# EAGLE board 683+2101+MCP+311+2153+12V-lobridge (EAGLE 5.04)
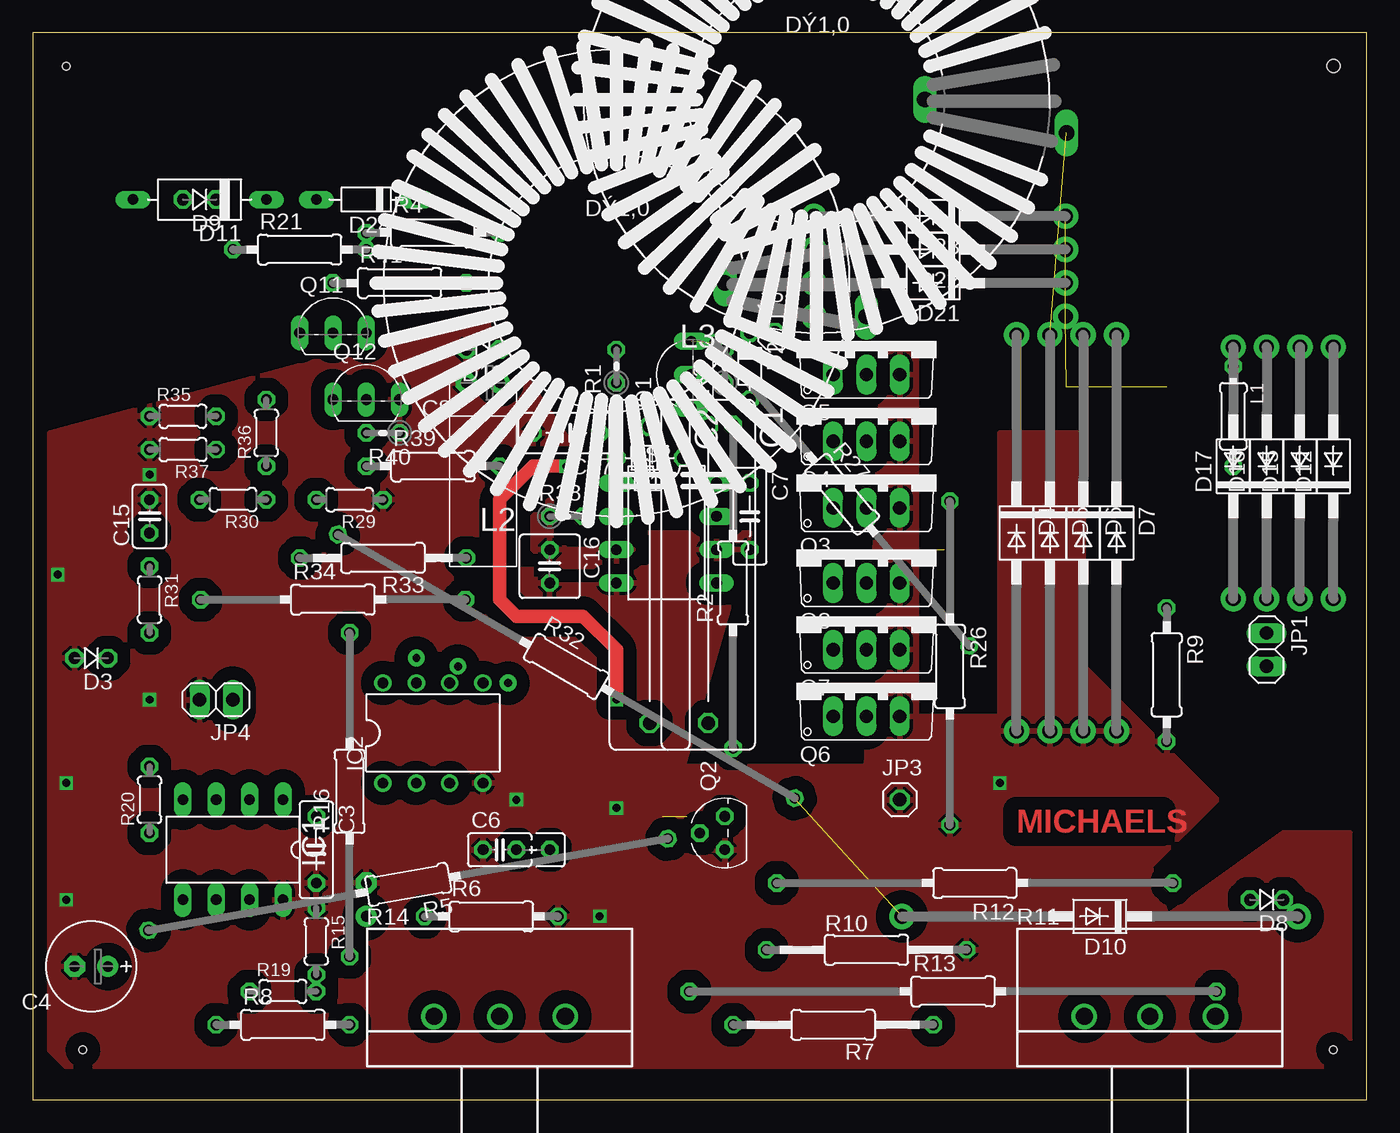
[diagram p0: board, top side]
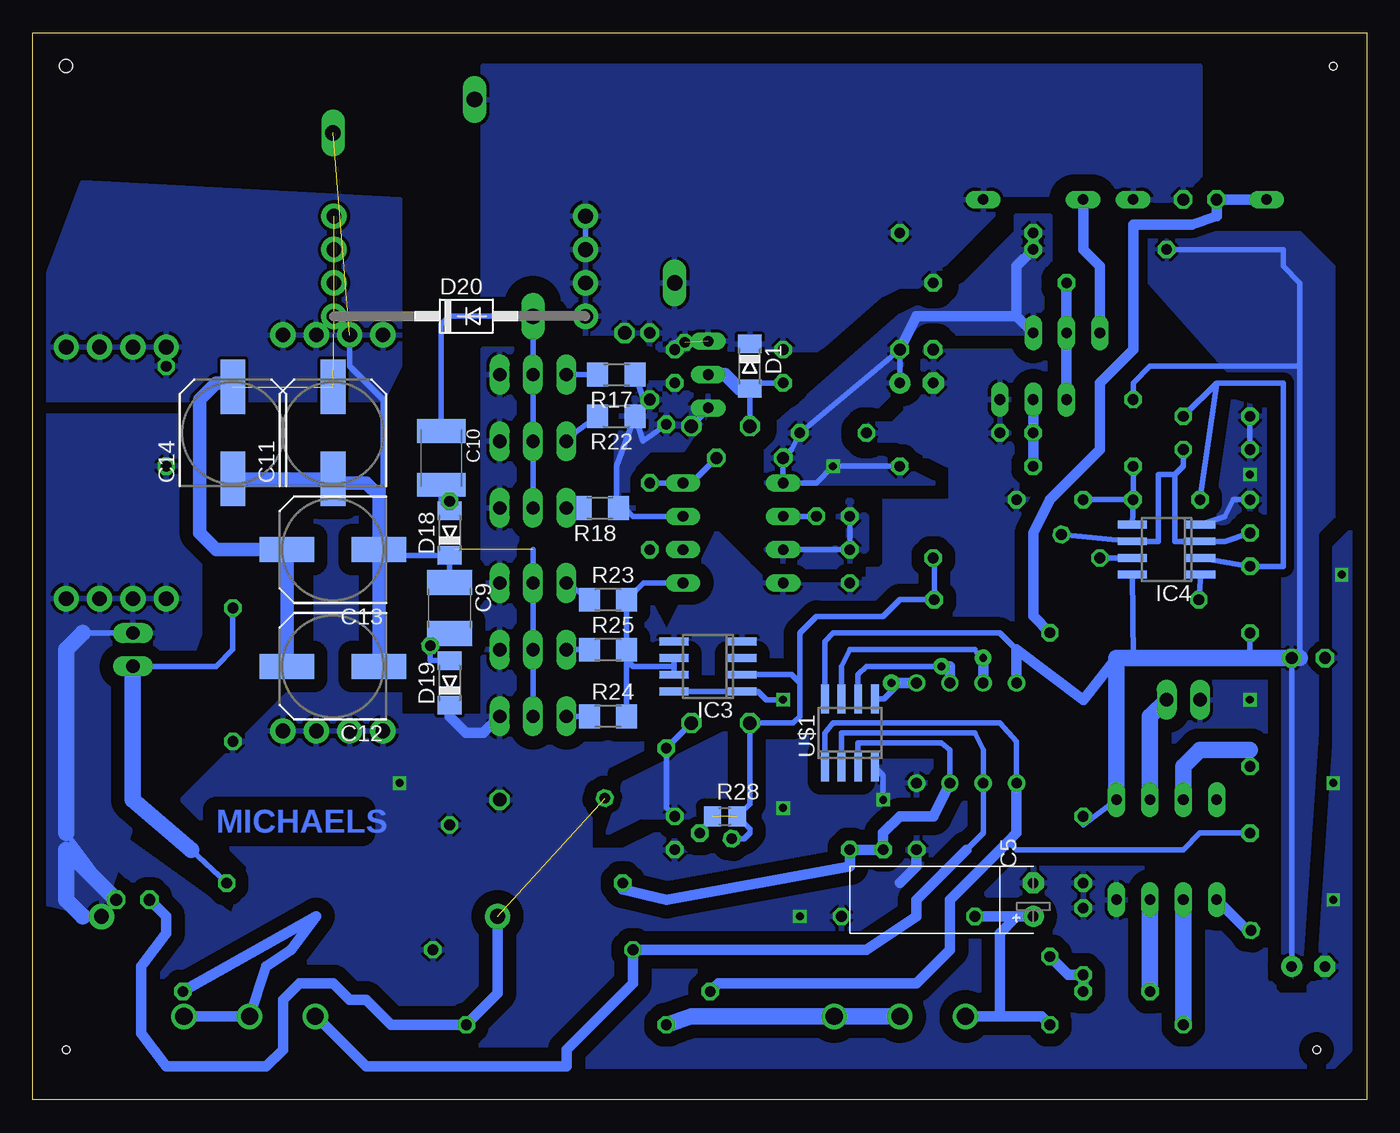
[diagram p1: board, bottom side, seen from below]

Size 101.6 x 81.28 mm. Coordinates in mm from the lower left corner, seen from the top.
Outline: 0,0 101.6,0 101.6,81.28 0,81.28 0,0
Copper layers (1*16): Top 0.035mm / dielectric 1.5mm / Bottom 0.035mm
Design rules "default": minimum track width 10mil, minimum drill 24mil, track to track 8mil, track to pad 8mil, pad to pad 8mil, via to via 8mil, smd to smd 8mil, copper to edge 40mil, drill to drill 8mil, minimum pad ring 10mil, minimum via ring 8mil, stop-mask expansion 4mil, vias tented up to drill 0mil, thermal gap 10mil
Holes 0.6 mm at 2.54,78.74 3.81,3.81 99.06,3.81
Holes 1 mm at 99.06,78.74

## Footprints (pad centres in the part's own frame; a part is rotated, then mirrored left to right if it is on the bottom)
C225-074X268 = drill 1.016 octagon: 1 -11.303,0; 2 11.303,0
C225-062X268 = drill 1.016 octagon: 1 -11.303,0; 2 11.303,0
C050-025X075 = drill 0.813 octagon: 1 -2.54,0; 2 2.54,0
E2,5-7 = drill 0.813 pad 1.6 round: + -1.27,0 | drill 0.813 pad 1.6 octagon: - 1.27,0
2,5-5-FLAT = drill 0.813 pad 1.6 round: + -1.27,0 | drill 0.813 pad 1.6 octagon: - 1.27,0
C025_050-025X075 = drill 0.813 octagon: 1 -1.27,0; 2 1.27,0; 3 3.81,0
C1812 = smd 1.9 x 3.4: 1 -1.95,0; 2 1.95,0
C1812K = smd 1.8 x 3.7: 1 -2.05,0; 2 2.05,0
SANYO-OSCON_SMD_E7 = smd 4.15 x 1.9: + 3.5,0; - -3.5,0
C025-025X050 = drill 0.813 octagon: 1 -1.27,0; 2 1.27,0
C025-050X050 = drill 0.813 octagon: 1 -1.27,0; 2 1.27,0
C050-030X075 = drill 0.813 octagon: 1 -2.54,0; 2 2.54,0
MINIMELF = smd 1.4 x 1.8: A 1.7,0; C -1.7,0
D-5 = drill 0.9 octagon: A 2.54,0; C -2.54,0
D-2.5 = drill 0.9 octagon: A 1.27,0; C -1.27,0
DO41-30 = drill 1.118 pad 1.93 round: A 15.08,0; C -15.08,0
D-10 = drill 0.813 long: A 5.08,0; C -5.08,0
DO41-20 = drill 1.118 pad 1.93 round: A 9.08,0; C -10.08,0
D-7.5 = drill 0.813 long: A 3.81,0; C -3.81,0
DIL8 = drill 0.813 long: 1 -3.81,-3.81; 2 -1.27,-3.81; 3 1.27,-3.81; 4 3.81,-3.81; 5 3.81,3.81; 6 1.27,3.81; 7 -1.27,3.81; 8 -3.81,3.81
DIL08 = drill 0.813 pad 1.27 round: 1 -3.81,-3.81; 2 -1.27,-3.81; 3 1.27,-3.81; 4 3.81,-3.81; 5 3.81,3.81; 6 1.27,3.81; 7 -1.27,3.81; 8 -3.81,3.81
SO-08 = smd 0.6 x 2.2: 1 -1.905,-2.6; 2 -0.635,-2.6; 3 0.635,-2.6; 4 1.905,-2.6; 5 1.905,2.6; 6 0.635,2.6; 7 -0.635,2.6; 8 -1.905,2.6
SO08 = smd 0.6 x 2.2: 1 -1.905,-2.6; 2 -0.635,-2.6; 3 0.635,-2.6; 4 1.905,-2.6; 5 1.905,2.6; 6 0.635,2.6; 7 -0.635,2.6; 8 -1.905,2.6
1X02 = drill 1.016 long: 1 -1.27,0; 2 1.27,0
1X01 = drill 1.016 octagon: 1 0,0
0204/7 = drill 0.813 octagon: 1 -3.81,0; 2 3.81,0
RKE2 = drill 1.194 long: 1 -19.05,2.54; 2 -8.255,0
TO92-EBC = drill 0.813 long: B 0,-1.27; C -2.54,-1.27; E 2.54,-1.27
TO-92 = drill 0.813 octagon: 1 -1.27,0; 2 0,1.905; 3 1.27,0
TO220V = drill 1.016 long: 1 -2.54,-2.54; 2 0,-2.54; 3 2.54,-2.54
0204V = drill 0.813 octagon: 1 -1.27,0; 2 1.27,0
0207/25 = drill 0.813 octagon: 1 -12.58,0; 2 12.08,0
0207/10 = drill 0.813 octagon: 1 -5.08,0; 2 5.08,0
0207/40 = drill 0.813 octagon: 1 -20.08,0; 2 20.08,0
0207/15 = drill 0.813 octagon: 1 -7.62,0; 2 7.62,0
CIP20C-4MM = drill 1.3 pad 1.93 round: A -5,0; E 5,0; S 0,0
0207/30 = drill 0.813 octagon: 1 -15.08,0; 2 15.08,0
0204/5 = drill 0.813 octagon: 1 -2.54,0; 2 2.54,0
R1206 = smd 1.6 x 1.803: 1 -1.422,0; 2 1.422,0
R0805 = smd 1.3 x 1.5: 1 -0.95,0; 2 0.95,0
0207/12 = drill 0.813 octagon: 1 -6.35,0; 2 6.35,0
0207/20 = drill 0.813 octagon: 1 -10.08,0; 2 10.08,0
DIL08' = drill 0.813 long: 1 -3.81,-3.81; 2 -1.27,-3.81; 3 1.27,-3.81; 4 3.81,-3.81; 5 3.81,3.81; 6 1.27,3.81; 7 -1.27,3.81; 8 -3.81,3.81

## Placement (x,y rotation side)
C1  [C225-074X268]  51.44,40.01 270 top
C2  [C225-062X268]  46.99,40.01 270 top
C3  [C050-025X075]  21.59,19.05 270 top
C4  [E2,5-7]  4.45,10.16 180 top
C5  [2,5-5-FLAT]  25.4,15.24 90 bottom
C6  [C025_050-025X075]  35.56,19.05 0 top
C7  0u1  [C050-025X075]  54.61,44.45 270 top
C8  [2,5-5-FLAT]  34.29,54.61 180 top
C9  [C1812]  69.85,37.47 270 bottom
C10  [C1812K]  70.48,48.9 270 bottom
C11  [SANYO-OSCON_SMD_E7]  78.74,50.8 90 bottom
C12  [SANYO-OSCON_SMD_E7]  78.74,33.02 180 bottom
C13  [SANYO-OSCON_SMD_E7]  78.74,41.91 180 bottom
C14  [SANYO-OSCON_SMD_E7]  86.36,50.8 90 bottom
C15  [C025-025X050]  8.89,44.45 90 top
C16  0u1  [C025-050X050]  39.37,40.64 270 top
C17  0u1  [C050-030X075]  40.64,50.8 180 top
D1  1N4148MINIMELF  [MINIMELF]  46.99,55.88 270 bottom
D2  [D-5]  54.61,55.88 270 top
D3  [D-2.5]  4.45,33.66 180 top
D4  1N400430  [DO41-30]  74.93,43.18 270 top
D5  1N400430  [DO41-30]  77.47,43.18 270 top
D6  1N400430  [DO41-30]  80.01,43.18 270 top
D7  1N400430  [DO41-30]  82.55,43.18 270 top
D8  [D-2.5]  93.98,15.24 180 top
D9  [D-2.5]  12.7,68.58 180 top
D10  [DO41-30]  81.28,13.97 180 top
D11  [D-10]  12.7,68.58 180 top
D12  1N400420  [DO41-20]  99.06,48.26 90 top
D13  [D-2.5]  34.29,57.15 180 top
D14  [D-5]  46.99,48.9 180 top
D15  1N400420  [DO41-20]  96.52,48.26 90 top
D16  1N400420  [DO41-20]  93.98,48.26 90 top
D17  1N400420  [DO41-20]  91.44,48.26 90 top
D18  1N4148MINIMELF  [MINIMELF]  69.85,43.18 90 bottom
D19  1N4148MINIMELF  [MINIMELF]  69.85,31.75 90 bottom
D20  1N400420  [DO41-20]  68.58,59.69 0 bottom
D21  1N400420  [DO41-20]  68.58,62.23 180 top
D22  1N400420  [DO41-20]  68.58,64.77 180 top
D23  1N400420  [DO41-20]  68.58,67.31 180 top
D24  [D-7.5]  25.4,68.58 180 top
IC1  PIC12F675P  [DIL8]  15.24,19.05 180 top
IC2  LM358N  [DIL08]  30.48,27.94 0 top
IC3  TC4432X  [SO-08]  50.16,33.02 90 bottom
IC4  LM393D  [SO08]  15.24,41.91 90 bottom
JP1  [1X02]  93.98,34.29 270 top
JP2  [1X01]  56.52,58.42 0 top
JP3  [1X01]  66.04,22.86 0 top
JP4  [1X02]  13.97,30.48 180 top
L1  [0204/7]  91.44,52.07 270 top
L2  RKE2  [RKE2]  44.45,62.23 180 top
L3  RKE2  [RKE2]  59.69,76.2 180 top
Q1  BC327-40  [TO92-EBC]  48.9,55.24 90 top
Q2  mpsa44  [TO-92]  52.7,20.32 90 top
Q3  IRF9530TO220V  [TO220V]  63.5,47.62 0 top
Q4  IRF9530TO220V  [TO220V]  63.5,52.7 0 top
Q5  IRF9530TO220V  [TO220V]  63.5,57.78 0 top
Q6  IRF840TO220V  [TO220V]  63.5,31.75 0 top
Q7  IRF840TO220V  [TO220V]  63.5,36.83 0 top
Q8  IRF840TO220V  [TO220V]  63.5,41.91 0 top
Q11  BC338-40  [TO92-EBC]  22.86,59.69 0 top
Q12  BC338-40  [TO92-EBC]  25.4,54.61 0 top
R1  [0204V]  44.45,55.88 90 top
R2  [0207/25]  53.34,39.37 90 top
R3  [0204V]  52.7,55.88 90 top
R4  [0207/10]  30.48,66.04 0 top
R5  [0207/40]  28.58,16.4 190 top
R6  [0207/10]  34.92,13.97 0 top
R7  [0207/15]  60.96,5.71 180 top
R8  [0207/10]  19.05,5.71 0 top
R9  [0207/10]  86.36,32.38 270 top
R10  [0207/15]  63.5,11.43 0 top
R11  [CIP20C-4MM]  85.09,6.35 0 top
R12  [0207/30]  71.75,16.51 180 top
R13  [0207/40]  70.09,8.26 0 top
R14  [CIP20C-4MM]  35.56,6.35 0 top
R15  [0204/5]  21.59,12.06 270 top
R16  [0207/25]  24.13,23.5 90 top
R17  [R1206]  57.15,55.24 180 bottom
R18  [R1206]  58.42,45.09 180 bottom
R19  [0204/5]  19.05,8.26 0 top
R20  [0204/5]  8.89,22.86 90 top
R21  [0207/10]  20.32,64.77 0 top
R22  [R1206]  57.15,52.07 180 bottom
R23  [R1206]  57.78,38.1 0 bottom
R24  [R1206]  57.78,29.21 0 bottom
R25  [R1206]  57.78,34.29 0 bottom
R26  [0207/25]  69.85,33.02 270 top
R27  [0207/30]  61.63,46.14 310 top
R28  [R0805]  48.9,21.59 0 bottom
R29  [0204/5]  24.13,45.72 180 top
R30  [0204/5]  15.24,45.72 180 top
R31  [0204/5]  8.89,38.1 270 top
R32  [0207/40]  40.64,33.02 330 top
R33  [0207/12]  26.67,41.27 180 top
R34  [0207/20]  22.86,38.1 0 top
R35  [0204/5]  11.43,52.07 0 top
R36  [0204/5]  17.78,50.8 90 top
R37  [0204/5]  11.43,49.53 180 top
R38  [0204V]  40.64,44.45 0 top
R39  [0207/10]  30.48,48.26 0 top
R40  [0204V]  26.67,50.8 180 top
R41  [0207/10]  27.94,62.23 0 top
U$1  MCP6042SOIC  [SO-08]  39.37,27.94 0 bottom
U$2  IR2153DIL8  [DIL08']  48.26,43.18 270 top

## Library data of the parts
C1-C17 L1 R1-R10 R12 R13 R15-R41 = rcl-2
D1-D24 = diode-1
IC1 = microchip-5
IC2 IC4 = linear
IC3 = microchip
JP1-JP4 = pinhead
L2 L3 = inductors
Q1 = transistor-pnp
Q2-Q8 = transistor-fet
Q11 Q12 = transistor-npn
R11 R14 = pot
U$1 = microchip-3
U$2 = irf-2

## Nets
BB: C2.2 IC3.2 Q2.2 R5.1 R28.1 R28.2 R33.1 R34.2
CT: C16.1 R38.1 U$2.3
DRAIN: C9.1 C11.- C12.- C13.- C14.- D4.C D5.C D6.C D7.C D12.A D15.A D16.A D17.A D18.C L1.1 L3.1 Q6.2 Q7.2 Q8.2
GATE: C1.1 D2.A Q1.C R2.2 R3.1 R17.1 R18.1 R22.1 U$2.7
MPOINT: C5.+ R6.1 R8.2 R14.A
N$1: C1.2 Q2.3 R2.1
N$2: IC2.6 U$1.6
N$3: IC1.5 R5.2
N$4: Q3.1 R18.2
N$5: IC1.6 R8.1
N$6: IC2.2 R10.1 R11.A U$1.2
N$7: IC2.1 R13.1 R20.1 U$1.1
N$9: C6.2 IC2.3 R12.2 U$1.3
N$10: R7.2 R14.E R14.S
N$11: Q5.1 R17.2
N$12: R15.2 R16.1 R19.2
N$13: D9.A D11.A R16.2
N$14: IC1.7 R19.1
N$15: IC1.2 JP4.1
N$16: D8.A D10.A R7.1 R32.2
N$17: IC1.3 R20.2
N$18: IC2.5 U$1.5
N$19: C15.1 IC4.3 IC4.6 R32.1 R37.1
N$20: IC2.7 U$1.7
N$21: C10.1 L2.1 Q3.2 Q4.2 Q5.2
N$22: IC4.7 R33.2
N$23: Q4.1 R22.2
N$24: C10.2 D18.A R26.1
N$25: Q7.1 R25.1
N$26: Q6.1 R24.1
N$27: Q8.1 R23.1
N$28: C9.2 D19.A R27.2
N$29: R11.E R11.S R13.2
N$30: IC4.1 R34.1
N$31: C11.+ C12.+ C13.+ C14.+ D20.C D21.C D22.C D23.C
N$32: IC4.5 R29.2 R30.1 R36.1
N$33: IC3.6 IC3.7 R23.2 R24.2 R25.2 U$2.5
N$34: IC4.2 R30.2 R31.1 R35.2
N$36: D24.A Q11.C
N$38: Q11.B Q12.C R41.1
N$40: R38.2 U$2.2
N$41: Q12.B R39.1 R40.2
OUT+: D8.C D10.C D12.C D15.C D16.C D17.C JP1.1 L1.2
OUT-: JP1.2 R9.1 R12.1
TB: C2.1 D1.A Q1.B R1.1
V+: C3.1 C4.+ D3.C IC1.1 IC2.8 IC4.8 R21.1 R31.2 R36.2 U$1.8
V-: C3.2 C4.- C5.- C6.1 C7.2 C8.- C15.2 C16.2 C17.2 D3.A D4.A D5.A D6.A D7.A D13.A D19.C IC1.8 IC2.4 IC3.4 IC3.5 IC4.4 JP3.1 JP4.2 Q2.1 Q3.3 Q4.3 Q5.3 Q6.3 Q7.3 Q8.3 Q12.E R6.2 R9.2 R10.2 R15.1 R26.2 R29.1 R35.1 R37.2 R40.1 U$1.4 U$2.4 U$2.6
VB: C7.1 D14.C U$2.8
VCC: C8.+ C17.1 D13.C D14.A IC3.1 IC3.8 Q11.E R4.1 R21.2 R39.2 U$2.1
VIN: D1.C D2.C D9.C D11.C D20.A D21.A D22.A D23.A D24.C JP2.1 L2.2 L3.2 Q1.E R1.2 R3.2 R4.2 R27.1 R41.2

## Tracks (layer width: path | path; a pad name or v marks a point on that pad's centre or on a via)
BB  (1 unrouted)
  Bottom 0.406: R5.1 47.42,19.89 46.99,20.32 46.99,20.64 R28.2 46.99,22.55 C2.2 43.69,28.7 43.18,29.21 43.18,31.75 | R28.1 Q2.2 | 43.18,31.75 43.81,32.38 IC3.2 | 43.18,31.75 43.18,35.56 41.91,36.83 36.83,36.83 35.56,38.1 R34.2 32.94,41.2 R33.1
CT
  Bottom 0.406: R38.1 C16.1 U$2.3
  pour Bottom (isolate 0.813, rank 3): 45.72,41.91 40.64,41.91 39.37,43.18 40.64,44.45 39.37,45.72 38.1,44.45 38.1,41.91 39.37,40.64 44.45,40.64
  pour Top (isolate 0.813, rank 3): 45.72,41.91 40.64,41.91 39.37,43.18 40.64,44.45 39.37,45.72 38.1,44.45 38.1,41.91 39.37,40.64 44.45,40.64
DRAIN  (2 unrouted)
  Bottom 0.406: D18.C C9.1 | Q6.2 Q7.2 Q8.2 63.5,41.91 | D18.C 69.42,41.91 | D18.C 74.5,41.48 74.93,41.91 C13.- | D5.C 77.47,55.88 74.93,53.34 74.93,43.49 75.24,43.18
  Bottom 1.016: C12.- C13.- 75.24,43.18 75.24,46.03 76.2,46.99 78.43,46.99 C11.- 86.05,47.3 86.36,46.99 C14.-
  pour Bottom (isolate 0.254, rank 5): 101.6,53.34 74.93,53.34 73.66,55.88 73.66,68.58 97.79,69.85 101.6,59.69
GATE
  Bottom 0.406: R18.1 57.15,45.09 57.15,45.72 | 57.15,45.72 57.15,48.26 R22.1 55.11,50.18 R2.2 | D2.A 55.09,53.34 R17.1 | U$2.7 55.88,44.45 57.15,45.72 | Q1.C 50.16,52.58 C1.1
  pour Bottom (isolate 0.813, rank 2): 49.53,53.34 50.8,54.61 53.34,54.61 54.61,54.61 57.15,52.07 57.15,44.45 55.88,44.45 55.88,48.26 54.61,49.53 52.07,49.53
MPOINT
  Bottom 0.813: R6.1 C5.+ 26.67,13.97 27.94,12.7 27.94,6.35 | 27.94,6.35 24.77,6.35 R8.2 | 27.94,6.35 R14.A
N$1
  Bottom 0.406: C1.2 R2.1 53.34,22.23 Q2.3
  pour Bottom (isolate 0.61, rank 3): 48.9,27.94 56.52,24.13 57.78,20.32 55.24,21.59 48.9,21.59
N$2  (via drill 0.6 pad 1.27)
  Bottom 0.406: U$1.6 38.73,32.38 38.1,33.02 v32.38,33.02 31.75,33.02
  Bottom 0.813: IC2.6 31.75,33.02
N$3
  Bottom 0.813: R5.2 9.1,12.91 IC1.5
N$4
  Bottom 0.406: R18.2 Q3.1
N$5
  Bottom 1.27: R8.1 IC1.6
N$6
  Bottom 0.406: 30.48,19.05 29.21,20.32 IC2.2 29.21,26.67 29.84,27.94 40.01,27.94 U$1.2
  Bottom 0.813: 30.48,19.05 34.29,15.24 34.29,13.97 38.1,11.43 R10.1 55.88,8.89 60.96,3.81 60.96,2.54 76.2,2.54 80.01,6.35 R11.A
N$7
  Bottom 0.406: U$1.1 41.27,27.94 40.64,28.7 27.94,28.7 26.67,27.3 IC2.1 | R20.1 12.7,20.32 13.97,19.05 26.67,19.05 27.3,19.68
  Bottom 0.813: IC2.1 26.67,20.32 27.3,19.68 31.75,15.24 31.75,11.43 34.29,8.89 49.38,8.89 R13.1
N$8  (via drill 0.6 pad 1.27)
  other vias: 36.2,31.75
N$9
  Bottom 0.406: U$1.3 38.73,27.18 32.38,27.18 31.75,26.67 IC2.3
  Bottom 0.813: R12.2 56.67,16.04 53.34,15.24 39.37,17.78 39.37,19.05 C6.2 36.83,20.32 35.56,21.59 33.02,21.59 IC2.3
N$10
  Bottom 1.27: R14.S R14.E 51.44,6.35 R7.2
N$11
  Bottom 0.406: R17.2 Q5.1
N$12
  Bottom 0.813: R19.2 R15.2 22.74,9.53 R16.1
N$13
  Bottom 0.813: D11.A D9.A 11.43,67.31 13.34,66.67 17.78,66.67 17.78,57.15 20.32,54.61 20.32,49.53 24.13,45.72 25.4,43.18 25.4,36.84 R16.2
N$14
  Bottom 1.27: R19.1 IC1.7
N$15
  Bottom 1.27: IC1.2 16.51,29.21 JP4.1
N$16  (1 unrouted)
  Bottom 0.813: D8.A 91.44,13.97 91.44,12.7 93.34,10.16 93.34,5.08 91.44,2.54 83.82,2.54 82.55,3.81 82.55,7.62 81.28,8.89 78.74,8.89 77.47,7.62 76.2,7.62 74.3,5.71 R7.1 66.2,8.1 D10.A
N$17
  Bottom 0.406: R20.2 8.89,26.67
  Bottom 1.27: 8.89,26.67 12.7,26.67 13.97,25.4 IC1.3
N$18
  Bottom 0.406: U$1.5 36.77,30.54 35.56,31.75
  Bottom 0.813: IC2.5 35.56,31.75
N$19
  Bottom 0.406: C15.1 10.79,42.55 IC4.3 14.61,42.55 14.61,47.62 | R32.1 IC4.6 15.88,42.55 15.88,47.62 14.61,47.62 | R37.1 13.97,48.26 14.61,47.62
N$20
  Bottom 0.406: U$1.7 40.01,33.02 39.37,34.29 29.84,34.29 29.21,33.02
  Bottom 0.813: IC2.7 29.21,33.02
N$21
  Bottom 0.406: L2.1 Q5.2 Q4.2 Q3.2 | C10.1 70.48,59.05 69.85,59.69 L2.1 | L2.1 62.23,59.69
N$22
  Bottom 0.406: IC4.7 R33.2
N$23
  Bottom 0.406: R22.2 60.33,50.8 Q4.1
N$24
  Bottom 0.406: D18.A R26.1 70.48,45.6 C10.2
N$25
  Bottom 0.406: R25.1 Q7.1
N$26
  Bottom 0.406: R24.1 Q6.1
N$27
  Bottom 0.406: R23.1 Q8.1
N$28
  Bottom 0.406: C9.2 71.33,35.52 R27.2 71.33,33.45 D19.A
N$29
  Bottom 0.813: R13.2 80.01,13.97 81.92,11.43 83.82,10.16 R11.S R11.E
N$30
  Bottom 0.406: IC4.1 R34.1
N$31  (5 unrouted)
  Bottom 1.016: C12.+ C13.+ 87.63,41.91 88.9,43.18 88.9,53.34 87.63,54.61 86.67,54.61 C14.+
N$32
  Bottom 0.406: IC4.5 R30.1 | R30.1 R29.2 | R30.1 R36.1
N$33
  Bottom 0.406: IC3.7 52.77,33.02 | 52.77,33.02 IC3.6 | U$2.5 55.09,39.37 R23.2 R25.2 56.36,33.5 | 56.36,33.5 55.88,33.02 52.77,33.02 | 56.36,33.5 R24.2
N$34
  Bottom 0.406: 11.43,54.61 R30.2 | 11.43,54.61 6.35,54.61 6.35,40.64 R31.1 IC4.2 | 11.43,54.61 R35.2
N$35  (via drill 0.6 pad 1.27)
  other vias: 29.21,33.66
N$36
  Bottom 0.813: D24.A 21.59,64.77 20.32,63.5 Q11.C
N$38
  Bottom 0.813: R41.1 Q11.B Q12.C
N$40
  Bottom 0.406: R38.2 U$2.2
N$41
  Bottom 0.813: Q12.B R40.2 R39.1
OUT+
  Bottom 0.406: 97.79,35.56 JP1.1 | D8.C 99.06,20.32 | D10.C 97.79,13.97
  Bottom 1.27: 97.79,35.56 99.06,34.29 99.06,20.32 | D8.C 99.06,19.05 99.06,15.24 97.79,13.97
  pour Bottom (isolate 1.016, rank 5): 88.9,52.07 101.6,52.07 101.6,15.24 96.52,13.97 88.9,35.56
OUT-
  Bottom 0.406: R12.1 89.53,19.05 | JP1.2 87.63,33.02 86.36,34.29 R9.1
  Bottom 1.27: 89.53,19.05 93.98,22.86 JP1.2
TB
  Bottom 0.406: R1.1 46.56,54.61 D1.A C2.1
  Bottom 1.016: D1.A 47.83,54.18 48.9,55.24 Q1.B
V+
  Bottom 0.406: R21.1 6.35,64.77 6.35,63.5 5.08,62.23 5.08,55.88 | 5.08,34.29 5.08,55.88 | 5.08,34.29 D3.C C4.+ | 5.08,34.29 5.08,33.66 | IC1.1 21.59,20.95 C3.1 | U$1.8 41.27,34.92 40.64,35.56 27.94,35.56 26.67,34.29 | 17.78,33.66 IC4.8 | 8.89,33.66 R31.2 | R36.2 17.78,54.61 16.51,55.88 5.08,55.88
  Bottom 0.813: 19.05,33.66 21.59,30.48 26.67,34.29 IC2.8
  Bottom 1.27: 5.08,33.66 D3.C 8.89,33.66 17.78,33.66 19.05,33.66 IC1.1
  pour Bottom (isolate 0.61, rank 3): 16.51,66.04 5.08,66.04 2.54,63.5 2.54,44.45 3.81,43.18 3.81,27.94 5.08,8.89 6.35,10.16 6.35,50.8 16.51,62.23
V-  (via drill 0.6)
  Bottom 0.406: IC4.4 10.79,44.45 10.16,45.72 C15.2 | v36.83,22.86 36.83,24.7 U$1.4 | R37.2 R35.1
  Bottom 0.813: C6.1 34.29,17.78 35.56,16.51 | D19.C 69.85,29.21 68.58,27.94 67.31,27.94 Q6.3
  other vias: 44.45,22.23 43.18,13.97 73.66,24.13 8.89,30.48 8.89,47.62 1.91,40.01 2.54,24.13 2.54,15.24
  pour Top (isolate 1.016, rank 5): 1.27,50.8 34.29,59.69 45.72,43.18 54.61,43.18 49.53,25.4 63.5,25.4 64.77,57.15 67.31,57.15 67.31,29.21 73.66,29.21 73.66,50.8 80.01,50.8 80.01,33.02 90.17,22.86 85.09,17.78 86.36,13.97 95.25,20.32 100.33,20.32 100.33,3.81 99.06,2.54 2.54,2.54 1.27,3.81
  pour Bottom (isolate 1.016, rank 5): 1.27,50.8 34.29,59.69 45.72,39.37 49.53,43.18 53.34,35.56 64.77,57.15 67.31,57.15 67.31,29.21 73.66,29.21 73.66,50.8 80.01,50.8 80.01,33.02 90.17,22.86 85.09,17.78 86.36,13.97 95.25,20.32 100.33,20.32 100.33,3.81 99.06,2.54 2.54,2.54 1.27,3.81
VB
  Bottom 0.406: C7.1 U$2.8 51.44,46.99 D14.C
VCC  (via drill 0.6)
  Top 1.016: v40.64,48.26 38.1,48.26 35.56,45.72 35.56,38.1 36.83,36.83 41.91,36.83 44.45,34.29 v44.45,30.48
  Bottom 0.406: IC3.8 IC3.1 46.35,31.11 45.72,30.48 v44.45,30.48 | C8.+ D13.C C17.1 43.81,49.53 D14.A U$2.1 41.91,46.99 v40.64,48.26 R39.2
  Bottom 0.813: 26.67,59.69 Q11.E | 26.67,59.69 26.67,63.5 R21.2 R4.1 | D13.C 34.29,59.69 26.67,59.69
  pour Bottom (isolate 1.27, rank 2): 24.13,67.31 26.67,67.31 26.67,66.04 30.48,62.23 35.56,59.69 45.72,50.8 45.72,46.99 33.02,46.99 40.64,50.8 39.37,50.8 35.56,54.61 35.56,55.88 33.02,58.42 25.4,58.42 25.4,59.69 24.13,60.96
VIN  (1 unrouted)
  Bottom 0.406: R27.1 52.7,57.69 R3.2 | D22.A D23.A
  pour Bottom (isolate 1.27, rank 3): 12.7,78.74 67.31,78.74 67.31,58.42 55.88,58.42 54.61,57.15 41.91,57.15 31.75,63.5 26.67,67.31 12.7,67.31

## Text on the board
Top: MICHAELS
Bottom: MICHAELS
